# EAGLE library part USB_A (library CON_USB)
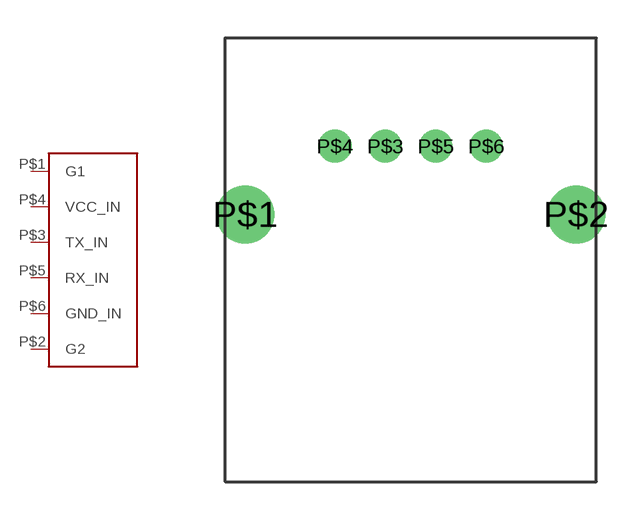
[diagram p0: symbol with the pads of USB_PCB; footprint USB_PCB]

Designator prefix -

## USB_A  [USB_PCB]
P$1  G1
P$2  G2
P$3  TX_IN  in
P$4  VCC_IN  pwr
P$5  RX_IN  in
P$6  GND_IN  pwr

## Footprint USB_PCB (pad centres in mm)
drill 1.5 pad 2.3 round: P$1 -6.55,3; P$2 6.55,3
drill 0.8 pad 0.95 round: P$3 -1,5.7; P$4 -3,5.7; P$5 1,5.7; P$6 3,5.7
